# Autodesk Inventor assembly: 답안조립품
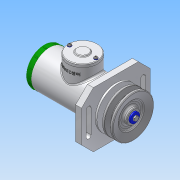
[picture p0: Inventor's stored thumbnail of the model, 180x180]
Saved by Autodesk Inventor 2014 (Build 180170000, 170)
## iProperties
Created: 2017-10
Part Number: 답안조립품
Document SubType Name: Assembly
Designer: user
Author: user
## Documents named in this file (20)
- C:\Users\user\Desktop\471007V1005\답안조립품.iam
- C:\Users\user\Desktop\471007V1005\본체.ipt
- C:\Users\user\Desktop\471007V1005\축.ipt
- C:\Users\user\Desktop\471007V1005\부시1.ipt
- C:\Users\user\Desktop\471007V1005\베어링 15 x 35 x 11.ipt
- C:\Users\user\Desktop\471007V1005\멈춤링 15 x 1.ipt
- C:\Users\user\Desktop\471007V1005\부시2.ipt
- C:\Users\user\Desktop\471007V1005\와셔 10x21.ipt
- C:\Users\user\Desktop\471007V1005\너트 M10.ipt
- C:\Users\user\Desktop\471007V1005\멈춤링 35x1.6.ipt
- C:\Users\user\Desktop\471007V1005\사이드 커버.ipt
- 사이드 커버.ipt
- C:\Users\user\Desktop\471007V1005\탑 커버.ipt
- C:\Users\user\Desktop\471007V1005\십자볼트 M3 x 10.ipt
- C:\Users\user\Desktop\471007V1005\와셔 3x6.ipt
- C:\Users\user\Desktop\471007V1005\오일 실 15 25 7.ipt
- C:\Users\user\Desktop\471007V1005\키 4 x 4 x 18.ipt
- C:\Users\user\Desktop\471007V1005\V-벨트풀리.ipt
- C:\Users\user\Desktop\471007V1005\와셔 4x16.ipt
- C:\Users\user\Desktop\471007V1005\볼트 M4 x 10.ipt
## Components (2 placed, 2 different names)
1. V-벨트풀리:1 — 각도:2
2. ISO 4017 M4 x 10:1
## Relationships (1: Angle 1)
- 각도:2 [Angle]: V-벨트풀리:1
